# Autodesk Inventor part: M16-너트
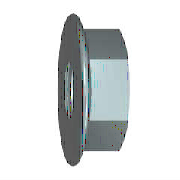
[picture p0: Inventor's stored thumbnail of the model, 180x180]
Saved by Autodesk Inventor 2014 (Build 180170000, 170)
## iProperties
IsCustomPart: 0
Company: 한국ATC센터
Created: 2009-02
Part Number: M16-너트
Material: Steel, Mild
Description: 플랜지붙이 6각 너트
Document SubType Name: Modeling
Standard: JIS B 1190
Designer: KYOUNG IL JANG
Standards Organization: JIS
Language: ko-KR
Size Designation: M 16
Categories: <MemberInstance><Categories><Category DisplayName="조임쇠" InternalName="e4da775c-781d-43d5-af7c-5136215cf5a6" Mnemonic="FSTN"><Category DisplayName="너트" InternalN
Density: 1 g/cm^3
Appearance: Metal-Steel
Author: KYOUNG IL JANG
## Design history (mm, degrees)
sketch "스케치1"
  geometry: L1 (-3.414, 0)-(18.069, 0) reference; L2 (6.015, 11)-(3.359, 15.6); L3 (6.015, 11)-(15, 11); L4 (15, 11)-(15, 0); L5 (6.015, 11)-(6.015, 0); L6 (0, -3.378)-(0, 20.266) reference; A1 r 1.8 centre (1.8, 14.7) between (3.359, 15.6) and (0, 14.7); 1 further point
  constraints: 8 end point, 3 point on line, 2 perpendicular, 2 point on circle, 2 tangent, 1 centre point, 1 parallel
  dimensions: "d2" = 22 diameter of L3 L1 (= SW); "d4" = 33 dimension on A1 L1 (= LADI); "d5" = 1.8 radius of A1 (= PHH); "d15" = 15 distance between parallel lines of L4 L6 (= KOH); "d16" = 30 deg angle of L6 L2 (= KEWI)
revolve "링" sketch "스케치1" stored, may be unused: angle "d8" = 90 deg
sketch "스케치2"
  geometry: L1 (-11, -6.351)-(-11, 6.351); L2 (-11, 6.351)-(0, 12.702); L3 (0, 12.702)-(11, 6.351); L4 (11, 6.351)-(11, -6.351); L5 (11, -6.351)-(0, -12.702); L6 (0, -12.702)-(-11, -6.351); C1 r 4.9 at (0, 0); C2 r 14.7 at (0, 0) reference; 1 further point
  constraints: 12 end point, 1 centre point, 1 coincident, 1 vertical, 11 other
  dimensions: "d6" = 25.40341 distance of L5.end L2.end (= 1.1547 x SW)
extrude "본체" join sketch "스케치2" distance "d7" = 15 (= KOH); taper "d9" = 0 deg
sketch "스케치3"
  geometry: L1 (5.032, 12.702)-(15, 12.702) reference; L2 (15, 6.351)-(15, 12.702) reference; L3 (0, -14.7)-(0, 14.7) reference; L4 (-3, 0)-(18, 0) reference; L5 (14.018, 12.702)-(15, 11)
  constraints: 2 end point, 2 point on line
  dimensions: "d10" = 30 deg angle of L2 L5 (= ANG1); "d11" = 22 diameter of L5.end L4 (= SW0)
revolve "모따기1" sketch "스케치3" stored, may be unused: angle "d24" = 90 deg
sketch "스케치4"
  geometry: C1 r 14.7 at (0, 0) reference; 1 further point
  constraints: 1 coincident
hole "스레드" sketch "스케치4" at (0, 0) diameter "d25" = 13.835; stored, may be unused: countersink angle "d29" = 82 deg, drill point angle "d31" = 118 deg; dims "d26" = 6, "d27" = 4, "d28" = 2, "d30" = 8
workaxis "Work Axis1"
workplane "Work Plane1"
body "Solid1"
chamfer "모따기2" distance "d12" = 1.08253 (= -0.5 x GD1 + 0.5 x NND); stored, may be unused: angle "d13" = 30 deg, second distance "d46" = 1.08253 (= -0.5 x GD1 + 0.5 x NND)
chamfer "모따기3" distance "d51" = 1.08253 (= -0.5 x GD1 + 0.5 x NND); stored, may be unused: second distance "d52" = 2, angle "d53" = 45 deg
other parameters: "ANG1" = 30 deg [user parameter; used in 1 equation term], "KEWI" = 30 deg [user parameter; used in 1 equation term], "NND" = 16 [user parameter; used in 3 equation terms], "LADI" = 33 [user parameter; used in 2 equation terms], "SW" = 22 [user parameter; used in 4 equation terms], "PHH" = 1.8 [user parameter; used in 2 equation terms], "KOH" = 15 [user parameter; used in 2 equation terms], "SW0" = 22 (= SW) [user parameter; used in 1 equation term], "GD1" = 13.83494 (computed from THREADDIA, PTC, TOA) [user parameter; used in 3 equation terms], "d1" = 33 (= LADI), "d3" = 1.8 (= PHH), "d45" = 0, "d47" = 0, "d49" = 0, "d54" = 0, "GUL" = 1.08253 (= 0.541266 x PTC) [user parameter], "TPU" = 5 (computed from PTC) [user parameter], "RR" = 2 [user parameter], "THREADDIA" = 16 [user parameter; used in 1 equation term], "TOA" = 30 deg [user parameter; used in 1 equation term], "PTC" = 2 [user parameter; used in 4 equation terms], "GAL" = 1.08253 (= 0.541266 x PTC) [user parameter], "E0" = 25.41 (= 1.155 x SW) [user parameter]
